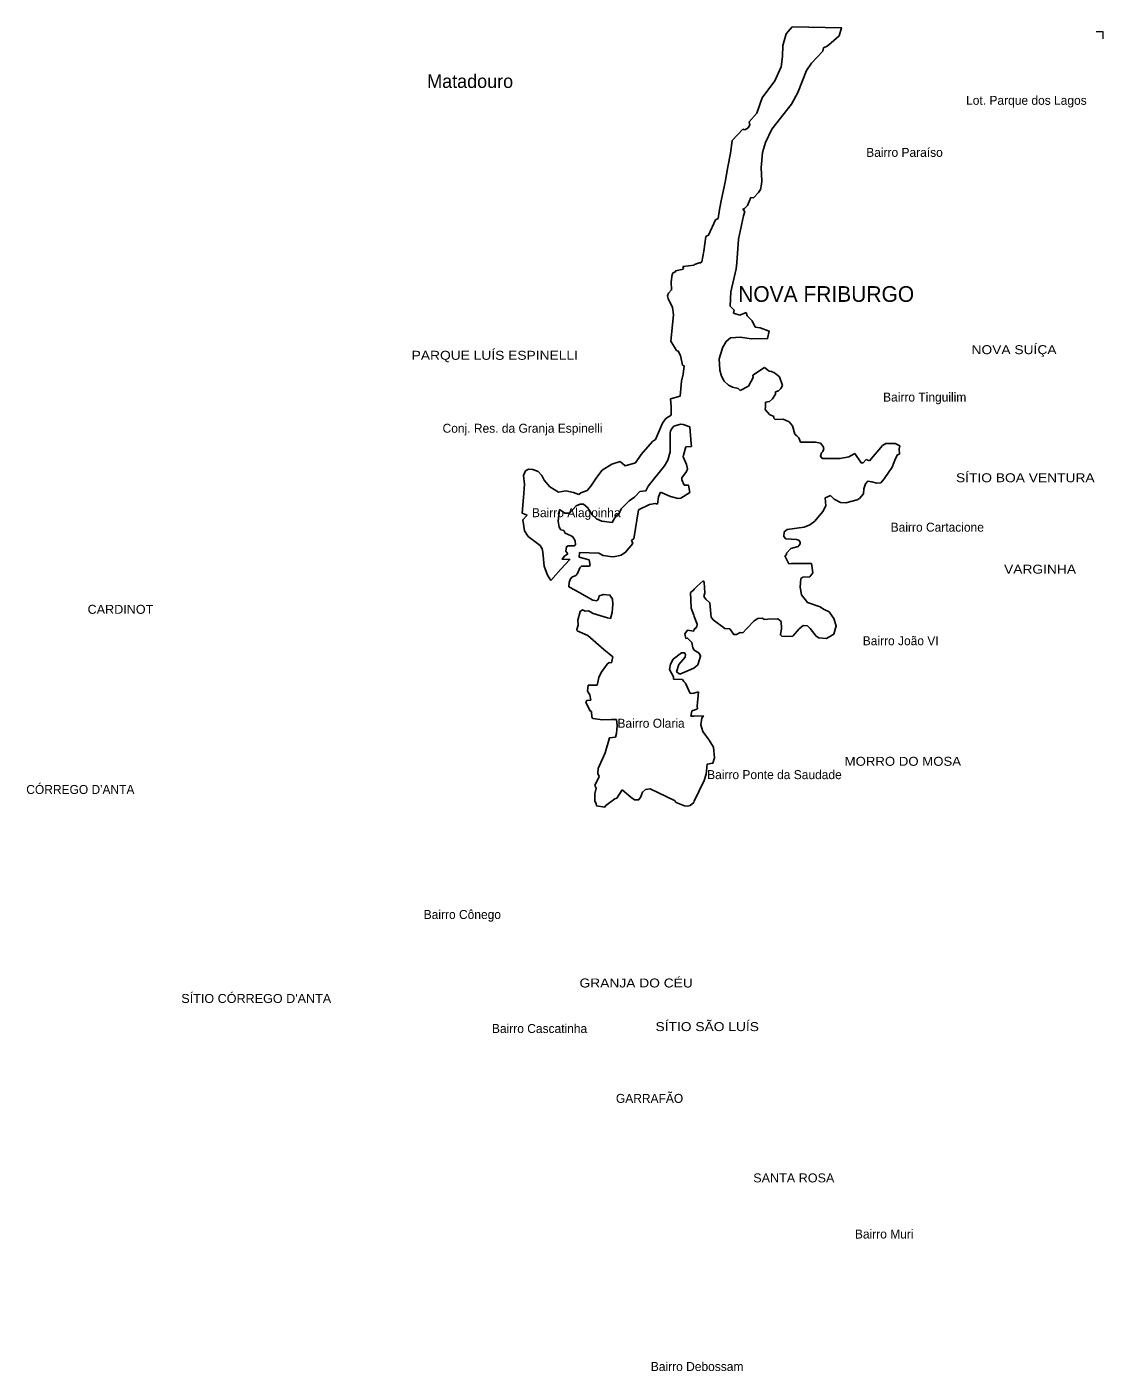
# Model space of a CAD drawing. Extents: x 731.5 to 757.7, y 7509.7 to 7537.8.
# Drawn here: x 748.05 to 757.66, y 7525.41 to 7537.41 of the extents above; entities that cross this region are included whole.
import ezdxf
from ezdxf.enums import TextEntityAlignment as Align

# ---------------------------------------------------------------- set-up
doc = ezdxf.new("R2010")
doc.units = 0
doc.header["$LTSCALE"] = 0.032
for name, color, linetype, lineweight in [('41', 7, 'Continuous', 25), ('62', 7, 'Continuous', 25), ('63', 7, 'Continuous', 13)]:
    doc.layers.add(name, color=color, linetype=linetype, lineweight=lineweight)
doc.layers.add('56', color=7, linetype='Continuous')
doc.layers.add('61', color=7, linetype='Continuous')

msp = doc.modelspace()

# ---------------------------------------------------------------- linework, layer by layer
at = {"layer": '41'}
for p, q in [((754.7934, 7537.1424), (754.7975, 7537.2419)), ((755.2289, 7537.2667), (755.3, 7537.3296)), ((754.3462, 7536.3953), (754.3314, 7536.2816)), ((754.3462, 7536.3953), (754.4417, 7536.4946)), ((754.4417, 7536.4946), (754.4579, 7536.4902)), ((754.3314, 7536.2816), (754.3072, 7536.1576)), ((754.2823, 7536.0226), (754.3072, 7536.1576)), ((754.6063, 7536.0056), (754.6094, 7536.0312)), ((754.4458, 7535.7203), (754.4018, 7535.5128)), ((754.0919, 7535.4064), (754.1108, 7535.5368)), ((754.4018, 7535.5128), (754.3861, 7535.3008)), ((754.0053, 7535.2816), (753.9051, 7535.2682)), ((753.9106, 7535.2552), (753.9051, 7535.2682)), ((754.0053, 7535.2816), (754.0086, 7535.2864)), ((753.7992, 7534.6032), (753.8226, 7534.8384)), ((754.3646, 7534.88), (754.329, 7534.9159)), ((754.3646, 7534.88), (754.3589, 7534.852)), ((754.4134, 7534.8336), (754.3589, 7534.852)), ((754.47, 7534.86), (754.4134, 7534.8336)), ((753.8472, 7534.5192), (753.7992, 7534.6032)), ((753.907, 7534.3072), (753.9177, 7534.3832)), ((754.5293, 7534.2992), (754.6336, 7534.3672)), ((754.4169, 7534.1616), (754.4916, 7534.2008)), ((753.7955, 7534.0888), (753.8819, 7534.1105)), ((753.7999, 7534.0208), (753.7955, 7534.0888)), ((753.7999, 7534.0208), (753.7996, 7533.9432)), ((754.6409, 7533.992), (754.6426, 7534.0168)), ((754.6426, 7534.0168), (754.6437, 7534.0584)), ((753.9801, 7533.6856), (753.9679, 7533.8392)), ((753.9097, 7533.584), (753.9323, 7533.6592)), ((753.9818, 7533.6628), (753.9323, 7533.6592)), ((753.9818, 7533.6628), (753.9801, 7533.6856)), ((754.9566, 7533.7016), (755.089, 7533.7016)), ((755.2112, 7533.5544), (755.3097, 7533.5568)), ((755.5421, 7533.5477), (755.5709, 7533.5349)), ((753.1859, 7533.4527), (753.1364, 7533.3896)), ((753.0837, 7533.3073), (753.1364, 7533.3896)), ((752.484, 7533.206), (752.4721, 7533.0688)), ((755.1754, 7533.2058), (755.1906, 7533.2112)), ((755.2228, 7533.2259), (755.1906, 7533.2112)), ((752.5154, 7533.0488), (752.4721, 7533.0688)), ((752.5154, 7533.0488), (752.4762, 7533.0096)), ((753.4684, 7532.8392), (753.5107, 7533.096)), ((752.4762, 7533.0096), (752.4906, 7532.9096)), ((753.4684, 7532.8392), (753.4466, 7532.8253)), ((753.4599, 7532.7968), (753.4466, 7532.8253)), ((752.8785, 7532.7042), (752.8481, 7532.6845)), ((752.9836, 7532.7174), (752.9792, 7532.6743)), ((752.9836, 7532.7174), (753.1551, 7532.7096)), ((754.8143, 7532.688), (754.8305, 7532.6944)), ((754.8143, 7532.688), (754.8528, 7532.6168)), ((752.8154, 7532.5667), (752.7266, 7532.4672)), ((753.0679, 7532.6509), (752.9792, 7532.6743)), ((754.8762, 7532.6176), (754.8528, 7532.6168)), ((754.8762, 7532.6176), (755.0546, 7532.6192)), ((752.8876, 7532.4088), (752.8917, 7532.4496)), ((752.9148, 7532.496), (752.9501, 7532.5126)), ((752.9385, 7532.3848), (752.8876, 7532.4088)), ((753.1529, 7532.3028), (753.1577, 7532.3293)), ((753.9999, 7532.3816), (754.0066, 7532.3904)), ((754.0066, 7532.3904), (754.0327, 7532.4149)), ((754.1111, 7532.2992), (754.0932, 7532.3224)), ((754.9654, 7532.3392), (754.9514, 7532.4064)), ((753.2324, 7532.132), (753.2591, 7532.1268)), ((754.0035, 7532.156), (754.0051, 7532.1448)), ((754.753, 7532.1248), (754.6653, 7532.1213)), ((753.9308, 7531.9488), (753.9223, 7531.992)), ((754.3258, 7532.0352), (754.2792, 7532.0384)), ((754.4395, 7532), (754.4738, 7532.036)), ((755.2532, 7531.988), (755.1884, 7531.9479)), ((753.2007, 7531.8522), (753.279, 7531.7864)), ((753.267, 7531.7328), (753.279, 7531.7864)), ((753.8493, 7531.6528), (753.8773, 7531.6312)), ((753.8773, 7531.6312), (754.0039, 7531.684)), ((753.1272, 7531.5328), (753.0599, 7531.5328)), ((753.1403, 7531.5327), (753.1272, 7531.5328)), ((753.9009, 7531.584), (753.8204, 7531.5872)), ((753.9009, 7531.584), (753.9152, 7531.5648)), ((754.0041, 7531.4624), (753.9707, 7531.4592)), ((754.0041, 7531.4624), (754.0441, 7531.4729)), ((754.0037, 7531.2568), (753.9758, 7531.256)), ((754.0037, 7531.2568), (754.0887, 7531.26)), ((754.0052, 7531.3101), (754.0368, 7531.3219)), ((753.2685, 7531.2264), (753.3135, 7531.225)), ((754.0848, 7531.1192), (754.1397, 7531.0408)), ((753.1578, 7530.7168), (753.121, 7530.6368)), ((753.3171, 7530.5224), (753.363, 7530.5984)), ((753.4418, 7530.5328), (753.363, 7530.5984)), ((754.0028, 7530.4848), (754.0049, 7530.4984))]:
    msp.add_line(p, q, dxfattribs=at)
for points in [[(754.7975, 7537.2419), (754.8279, 7537.3448), (754.8803, 7537.408), (754.8804, 7537.4081)], [(755.3233, 7537.4009), (755.3229, 7537.3998), (755.3, 7537.3296)], [(755.1601, 7537.2215), (755.1924, 7537.2352), (755.2289, 7537.2667)], [(755.1601, 7537.2215), (755.1555, 7537.1928), (755.0525, 7537.0832), (755.0082, 7537.0192), (754.9329, 7536.8224), (754.8749, 7536.7184), (754.7, 7536.4962)], [(754.7256, 7536.9259), (754.782, 7537.0528), (754.7934, 7537.1424)], [(754.5962, 7536.724), (754.6141, 7536.7752), (754.7256, 7536.9259)], [(754.5962, 7536.724), (754.5656, 7536.6376), (754.4973, 7536.5608)], [(754.4579, 7536.4902), (754.4877, 7536.5064), (754.5025, 7536.5344), (754.4973, 7536.5608)], [(754.7, 7536.4962), (754.6437, 7536.3752), (754.6159, 7536.2872), (754.6045, 7536.1528), (754.6094, 7536.0312)], [(754.2823, 7536.0226), (754.2513, 7535.8704), (754.2328, 7535.7794), (754.2193, 7535.6968)], [(754.6063, 7536.0056), (754.5975, 7535.956), (754.5802, 7535.9288), (754.5345, 7535.8832), (754.5128, 7535.8856)], [(754.442, 7535.7813), (754.4571, 7535.7863), (754.482, 7535.8128), (754.5128, 7535.8856)], [(754.2193, 7535.6968), (754.1969, 7535.6848), (754.1353, 7535.5488), (754.1108, 7535.5368)], [(754.4458, 7535.7203), (754.4573, 7535.7616), (754.442, 7535.7813)], [(754.0919, 7535.4064), (754.0735, 7535.3112), (754.0641, 7535.3016)], [(753.8412, 7535.224), (753.8175, 7535.2124), (753.8091, 7535.1976), (753.8007, 7535.1328)], [(753.9106, 7535.2552), (753.9075, 7535.2457), (753.8425, 7535.232), (753.8412, 7535.224)], [(754.0086, 7535.2864), (754.051, 7535.3032), (754.0641, 7535.3016)], [(754.329, 7534.9159), (754.3326, 7535.044), (754.3816, 7535.2496), (754.3861, 7535.3008)], [(753.7756, 7534.9824), (753.7676, 7535.0069), (753.7758, 7535.0322), (753.8047, 7535.06), (753.8007, 7535.1328)], [(753.7756, 7534.9824), (753.8137, 7534.9048), (753.8226, 7534.8384)], [(754.47, 7534.86), (754.4788, 7534.8304), (754.523, 7534.784), (754.5497, 7534.728)], [(754.2554, 7534.5349), (754.2596, 7534.5426), (754.2906, 7534.6), (754.3315, 7534.6328), (754.4201, 7534.6376), (754.5163, 7534.6248), (754.6624, 7534.6256), (754.6747, 7534.6936), (754.5953, 7534.7232), (754.5497, 7534.728)], [(753.9177, 7534.3832), (753.9026, 7534.3888), (753.885, 7534.4736), (753.8649, 7534.5136), (753.8472, 7534.5192)], [(754.2554, 7534.5349), (754.2548, 7534.5326), (754.2301, 7534.444), (754.2342, 7534.344), (754.2515, 7534.2896), (754.2747, 7534.2472), (754.3131, 7534.2104), (754.3481, 7534.1916)], [(754.6981, 7534.3321), (754.6748, 7534.336), (754.6336, 7534.3672)], [(753.907, 7534.3072), (753.8938, 7534.2463), (753.8819, 7534.1105)], [(754.4916, 7534.2008), (754.5322, 7534.2776), (754.5293, 7534.2992)], [(754.6981, 7534.3321), (754.7233, 7534.3216), (754.7667, 7534.284), (754.7956, 7534.208)], [(754.4169, 7534.1616), (754.3987, 7534.1792), (754.3481, 7534.1916)], [(754.7334, 7534.1504), (754.7333, 7534.1312), (754.7065, 7534.0896), (754.6778, 7534.064), (754.6437, 7534.0584)], [(754.7334, 7534.1504), (754.7601, 7534.1608), (754.7806, 7534.1792), (754.7956, 7534.208)], [(753.6618, 7533.7264), (753.7224, 7533.872), (753.7548, 7533.9136), (753.7996, 7533.9432)], [(754.6409, 7533.992), (754.6796, 7533.9472), (754.7184, 7533.9296)], [(754.7302, 7533.904), (754.7189, 7533.9168), (754.7184, 7533.9296)], [(754.7302, 7533.904), (754.8009, 7533.9056), (754.8533, 7533.8832), (754.8834, 7533.8464), (754.9042, 7533.7736), (754.9231, 7533.7568)], [(753.5221, 7533.2616), (753.5752, 7533.2672), (753.5949, 7533.3088), (753.7403, 7533.4896), (753.7703, 7533.5416), (753.7926, 7533.616), (753.7919, 7533.7792), (753.7951, 7533.804), (753.8088, 7533.8272), (753.8257, 7533.844), (753.8838, 7533.8616), (753.9091, 7533.86), (753.9679, 7533.8392)], [(754.9231, 7533.7568), (754.9412, 7533.7392), (754.9566, 7533.7016)], [(753.4819, 7533.5168), (753.5336, 7533.592), (753.6342, 7533.7072), (753.6618, 7533.7264)], [(755.089, 7533.7016), (755.1352, 7533.6912), (755.158, 7533.664), (755.1629, 7533.6408), (755.1563, 7533.6176), (755.1423, 7533.6055)], [(755.7833, 7533.6896), (755.716, 7533.6888), (755.6867, 7533.6712), (755.5709, 7533.5349)], [(755.8425, 7533.6696), (755.8004, 7533.6896), (755.7833, 7533.6896)], [(755.8425, 7533.6696), (755.8354, 7533.6408), (755.8393, 7533.5936)], [(753.3457, 7533.5288), (753.2718, 7533.504), (753.1859, 7533.4527)], [(753.4819, 7533.5168), (753.3916, 7533.4912), (753.3457, 7533.5288)], [(753.9097, 7533.584), (753.9075, 7533.5708), (753.9382, 7533.5013), (753.9463, 7533.4642), (753.939, 7533.4392), (753.8962, 7533.384), (753.8962, 7533.3648), (753.9162, 7533.3168)], [(755.2112, 7533.5544), (755.1503, 7533.556), (755.1328, 7533.5776), (755.1423, 7533.6055)], [(755.3097, 7533.5568), (755.3865, 7533.5712), (755.4398, 7533.6008)], [(755.5421, 7533.5477), (755.5164, 7533.5176), (755.497, 7533.5176), (755.4398, 7533.6008)], [(755.7728, 7533.4782), (755.8028, 7533.5552), (755.8227, 7533.5888), (755.8393, 7533.5936)], [(752.484, 7533.206), (752.4902, 7533.3256), (752.4832, 7533.4048), (752.4995, 7533.4465)], [(752.6678, 7533.3631), (752.6463, 7533.4025), (752.6134, 7533.44), (752.5664, 7533.4576), (752.5273, 7533.4592), (752.4995, 7533.4465)], [(755.5367, 7533.328), (755.5553, 7533.352), (755.5933, 7533.3488), (755.6363, 7533.3344), (755.6721, 7533.3384), (755.7033, 7533.3728), (755.7728, 7533.4782)], [(752.6678, 7533.3631), (752.7179, 7533.304), (752.7962, 7533.2552)], [(753.0837, 7533.3073), (753.0522, 7533.2688), (752.9931, 7533.2488), (752.9761, 7533.2352)], [(753.9162, 7533.3168), (753.9548, 7533.3184), (753.9682, 7533.2528)], [(755.5367, 7533.328), (755.5207, 7533.2856), (755.5173, 7533.2416)], [(752.7962, 7533.2552), (752.8609, 7533.2656), (752.9303, 7533.2528), (752.9761, 7533.2352)], [(753.425, 7533.1768), (753.355, 7533.1072), (753.3333, 7533.06)], [(753.5221, 7533.2616), (753.4749, 7533.2096), (753.425, 7533.1768)], [(753.6794, 7533.1488), (753.6882, 7533.2128), (753.7061, 7533.2552)], [(753.7061, 7533.2552), (753.7938, 7533.216), (753.8634, 7533.1992), (753.8875, 7533.2016), (753.9682, 7533.2528)], [(755.1754, 7533.2058), (755.1826, 7533.1328), (755.1563, 7533.0816), (755.0835, 7532.9952), (755.04, 7532.9648), (754.9891, 7532.9432)], [(755.313, 7533.1624), (755.255, 7533.1928), (755.2228, 7533.2259)], [(755.5173, 7533.2416), (755.4821, 7533.1976), (755.4603, 7533.1856), (755.3601, 7533.16), (755.313, 7533.1624)], [(752.8442, 7532.912), (752.8167, 7532.92), (752.8001, 7532.9432), (752.7928, 7532.9968), (752.804, 7533.0992)], [(752.804, 7533.0992), (752.8512, 7533.068), (752.8946, 7533.0672), (752.9516, 7533.1336), (752.9896, 7533.1472), (753.0183, 7533.1472), (753.0572, 7533.1144), (753.0961, 7533.0536), (753.1356, 7533.0176), (753.181, 7532.9952), (753.2736, 7532.9856)], [(753.3333, 7533.06), (753.3099, 7533.0472), (753.2736, 7532.9856)], [(753.6794, 7533.1488), (753.6583, 7533.1536), (753.6083, 7533.144), (753.5107, 7533.096)], [(754.9891, 7532.9432), (754.8361, 7532.9232), (754.8091, 7532.9008), (754.8078, 7532.8584), (754.8237, 7532.8392), (754.9208, 7532.8336), (754.9405, 7532.8256), (754.9527, 7532.8096), (754.9523, 7532.7944), (754.9343, 7532.7688), (754.8686, 7532.752)], [(752.6306, 7532.7787), (752.5246, 7532.8592), (752.4906, 7532.9096)], [(752.8442, 7532.912), (752.8551, 7532.888), (752.9072, 7532.8657)], [(752.8785, 7532.7042), (752.8597, 7532.7296), (752.8652, 7532.7672), (752.8819, 7532.776), (752.9359, 7532.7768), (752.9468, 7532.7856), (752.9443, 7532.82), (752.9222, 7532.8554), (752.9072, 7532.8657)], [(753.4599, 7532.7968), (753.3947, 7532.7184), (753.3539, 7532.692), (753.2887, 7532.6792), (753.2564, 7532.6816), (753.1952, 7532.6912), (753.1551, 7532.7096)], [(752.6306, 7532.7787), (752.6482, 7532.7496), (752.6551, 7532.7184), (752.6669, 7532.5936)], [(752.8154, 7532.5667), (752.896, 7532.6552), (752.8278, 7532.6576), (752.8481, 7532.6845)], [(754.8686, 7532.752), (754.8295, 7532.7104), (754.8305, 7532.6944)], [(752.7266, 7532.4672), (752.6959, 7532.5152), (752.6669, 7532.5936)], [(752.9501, 7532.5126), (752.9646, 7532.5291), (752.9843, 7532.5811), (753.0001, 7532.5944), (753.0669, 7532.596)], [(753.0679, 7532.6509), (753.0776, 7532.6016), (753.0669, 7532.596)], [(755.0546, 7532.6192), (755.0665, 7532.5336), (755.0387, 7532.5008), (754.975, 7532.496), (754.9578, 7532.484), (754.9514, 7532.4064)], [(752.9148, 7532.496), (752.8996, 7532.4768), (752.8917, 7532.4496)], [(754.0327, 7532.4149), (754.0866, 7532.4632), (754.0961, 7532.4504), (754.1013, 7532.3552), (754.0932, 7532.3224)], [(753.1529, 7532.3028), (753.1363, 7532.2864), (753.1013, 7532.2912), (752.9385, 7532.3848)], [(753.1577, 7532.3293), (753.1967, 7532.3404), (753.254, 7532.337), (753.2773, 7532.3008), (753.2817, 7532.256), (753.2743, 7532.1816), (753.2591, 7532.1268)], [(753.9999, 7532.3816), (753.9737, 7532.3592), (753.9787, 7532.2208), (754.0035, 7532.156)], [(754.9654, 7532.3392), (755.0171, 7532.2704), (755.1317, 7532.232), (755.1619, 7532.2094)], [(752.9706, 7532.0682), (752.9692, 7532.112), (752.9897, 7532.1904), (753.008, 7532.2034), (753.0318, 7532.1928)], [(753.0318, 7532.1928), (753.0625, 7532.1952), (753.1052, 7532.1712), (753.2324, 7532.132)], [(754.1111, 7532.2992), (754.1465, 7532.2664), (754.154, 7532.1688)], [(755.2532, 7531.988), (755.2736, 7532.0608), (755.253, 7532.1272), (755.2103, 7532.188), (755.1619, 7532.2094)], [(754.0051, 7532.1448), (754.0342, 7532.076), (754.0315, 7532.0568), (754.0156, 7532.036)], [(754.154, 7532.1688), (754.1583, 7532.1392), (754.1752, 7532.1168), (754.2792, 7532.0384)], [(754.6653, 7532.1213), (754.6304, 7532.12), (754.6172, 7532.1304), (754.5758, 7532.128), (754.542, 7532.1064), (754.4738, 7532.036)], [(754.7868, 7532.0368), (754.7827, 7532.1), (754.753, 7532.1248)], [(752.9706, 7532.0682), (752.9585, 7532.0296), (752.9627, 7532.0176), (753.0566, 7531.976), (753.2007, 7531.8522)], [(753.9223, 7531.992), (753.9457, 7532.0224), (754.0043, 7532.0152)], [(754.0043, 7532.0152), (754.0073, 7532.0352), (754.0156, 7532.036)], [(754.3258, 7532.0352), (754.3602, 7531.9832), (754.3844, 7531.984), (754.4159, 7532.0032), (754.4395, 7532)], [(754.8244, 7531.9664), (754.7876, 7531.9688), (754.7761, 7531.9816), (754.7868, 7532.0368)], [(754.8244, 7531.9664), (754.887, 7531.9688), (754.9435, 7532.0352)], [(754.9435, 7532.0352), (754.9795, 7532.064), (755.0166, 7532.0608), (755.0408, 7532.0368)], [(755.1884, 7531.9479), (755.1197, 7531.9544), (755.094, 7531.9688), (755.0408, 7532.0368)], [(753.9308, 7531.9488), (753.947, 7531.9528), (753.9866, 7531.9128), (753.993, 7531.8664), (754.0053, 7531.844)], [(754.0039, 7531.684), (754.04, 7531.7152), (754.0642, 7531.7912), (754.0508, 7531.8176), (754.0053, 7531.844)], [(753.267, 7531.7328), (753.2479, 7531.7352), (753.2296, 7531.7208), (753.1772, 7531.6457)], [(753.7863, 7531.6728), (753.7941, 7531.72), (753.8181, 7531.7632), (753.8934, 7531.82), (753.9201, 7531.82), (753.9303, 7531.8048), (753.9262, 7531.7832), (753.8703, 7531.716), (753.8493, 7531.6528)], [(753.1403, 7531.5327), (753.1565, 7531.6), (753.1772, 7531.6457)], [(753.7863, 7531.6728), (753.8213, 7531.6064), (753.8204, 7531.5872)], [(753.085, 7531.3992), (753.0747, 7531.4448), (753.0555, 7531.4792), (753.0599, 7531.5328)], [(753.9152, 7531.5648), (753.9285, 7531.5512), (753.9707, 7531.4592)], [(753.085, 7531.3992), (753.0478, 7531.3952), (753.0391, 7531.3784), (753.0777, 7531.3032), (753.0885, 7531.2984)], [(754.0368, 7531.3219), (754.0325, 7531.3455), (754.0441, 7531.4729)], [(753.2685, 7531.2264), (753.1877, 7531.224), (753.1019, 7531.2344), (753.0931, 7531.2456), (753.0885, 7531.2984)], [(754.0052, 7531.3101), (753.9952, 7531.3059), (753.9851, 7531.3016), (753.9758, 7531.256)], [(754.0887, 7531.26), (754.0755, 7531.2368), (754.0661, 7531.1792), (754.0848, 7531.1192)], [(753.3135, 7531.225), (753.3193, 7531.1715), (753.3133, 7531.102), (753.3044, 7531.0688)], [(753.3044, 7531.0688), (753.2514, 7531.0632), (753.2119, 7530.9288), (753.1485, 7530.788), (753.1467, 7530.7432), (753.1578, 7530.7168)], [(754.1397, 7531.0408), (754.1783, 7530.9792), (754.1881, 7530.884), (754.1728, 7530.8352), (754.1214, 7530.8272), (754.1148, 7530.7376), (754.0965, 7530.6824), (754.0049, 7530.4984)], [(753.121, 7530.6368), (753.1305, 7530.6128), (753.1197, 7530.5624), (753.1192, 7530.496), (753.1308, 7530.4776)], [(753.2095, 7530.4424), (753.2186, 7530.4584), (753.2981, 7530.5192), (753.3171, 7530.5224)], [(753.8303, 7530.5024), (753.6141, 7530.608), (753.572, 7530.6024), (753.5458, 7530.5784), (753.5273, 7530.5288), (753.5101, 7530.508), (753.4744, 7530.5088), (753.4418, 7530.5328)], [(753.1308, 7530.4776), (753.1339, 7530.4568), (753.2095, 7530.4424)], [(753.8303, 7530.5024), (753.8469, 7530.484), (753.919, 7530.456), (753.9454, 7530.4528), (753.9713, 7530.4576), (754.0028, 7530.4848)]]:
    msp.add_lwpolyline(points, dxfattribs=at)
at = {"layer": '62'}
msp.add_line((754.8804, 7537.4081), (755.3233, 7537.4009), dxfattribs=at)
at = {"layer": '63'}
msp.add_lwpolyline([(757.6571, 7537.3015), (757.6571, 7537.3631), (757.5964, 7537.3631)], dxfattribs=at)

# ---------------------------------------------------------------- texts
at = {"layer": '56'}
for s, width, p in [('PARQUE LUÍS ESPINELLI', 1.15, (752.2262, 7534.4366)), ('NOVA SUÍÇA', 1.15, (756.8618, 7534.4869)), ('SÍTIO BOA VENTURA', 1.15, (756.9624, 7533.3437)), ('VARGINHA', 1.15, (757.0941, 7532.5275)), ('CARDINOT', 1.05, (748.8846, 7532.1693)), ('MORRO DO MOSA', 1.1, (755.8692, 7530.8127)), ('GRANJA DO CÉU', 1.15, (753.4886, 7528.8341)), ("SÍTIO CÓRREGO D'ANTA", 1.05, (750.0968, 7528.6959)), ('SÍTIO SÃO LUÍS', 1.15, (754.123, 7528.4447)), ('SANTA ROSA', 1.05, (754.8958, 7527.0942))]:
    msp.add_text(s, height=0.08, dxfattribs=dict(at, width=width)).set_placement(p, align=Align.CENTER)
for s, p in [("CÓRREGO D'ANTA", (748.5266, 7530.5613)), ('GARRAFÃO', (753.6081, 7527.804))]:
    msp.add_text(s, height=0.08, dxfattribs=at).set_placement(p, align=Align.CENTER)
at = {"layer": '61'}
for s, height, p in [('Matadouro', 0.12, (751.6229, 7536.8632)), ('Lot. Parque dos Lagos', 0.08, (756.4341, 7536.7126)), ('Bairro Paraíso', 0.08, (755.5422, 7536.2478)), ('NOVA FRIBURGO', 0.14, (754.3994, 7534.9539)), ('Bairro Tinguilim', 0.08, (755.6927, 7534.0637)), ('Conj. Res. da Granja Espinelli', 0.08, (751.7603, 7533.7855)), ('Bairro Alagoinha', 0.08, (752.5582, 7533.0319)), ('Bairro Cartacione', 0.08, (755.7605, 7532.9024)), ('Bairro Olaria', 0.08, (753.3215, 7531.1524)), ('Bairro Ponte da Saudade', 0.08, (754.1223, 7530.6938)), ('Bairro Cônego', 0.08, (751.5918, 7529.4455)), ('Bairro Cascatinha', 0.08, (752.2011, 7528.4279)), ('Bairro Muri', 0.08, (755.4412, 7526.5934)), ('Bairro Debossam', 0.08, (753.6196, 7525.4109))]:
    msp.add_text(s, height=height, dxfattribs=at).set_placement(p)
msp.add_text('Bairro João VI', height=0.08, dxfattribs=at).set_placement((756.189, 7531.8887), align=Align.RIGHT)

doc.saveas('drawing.dxf')
